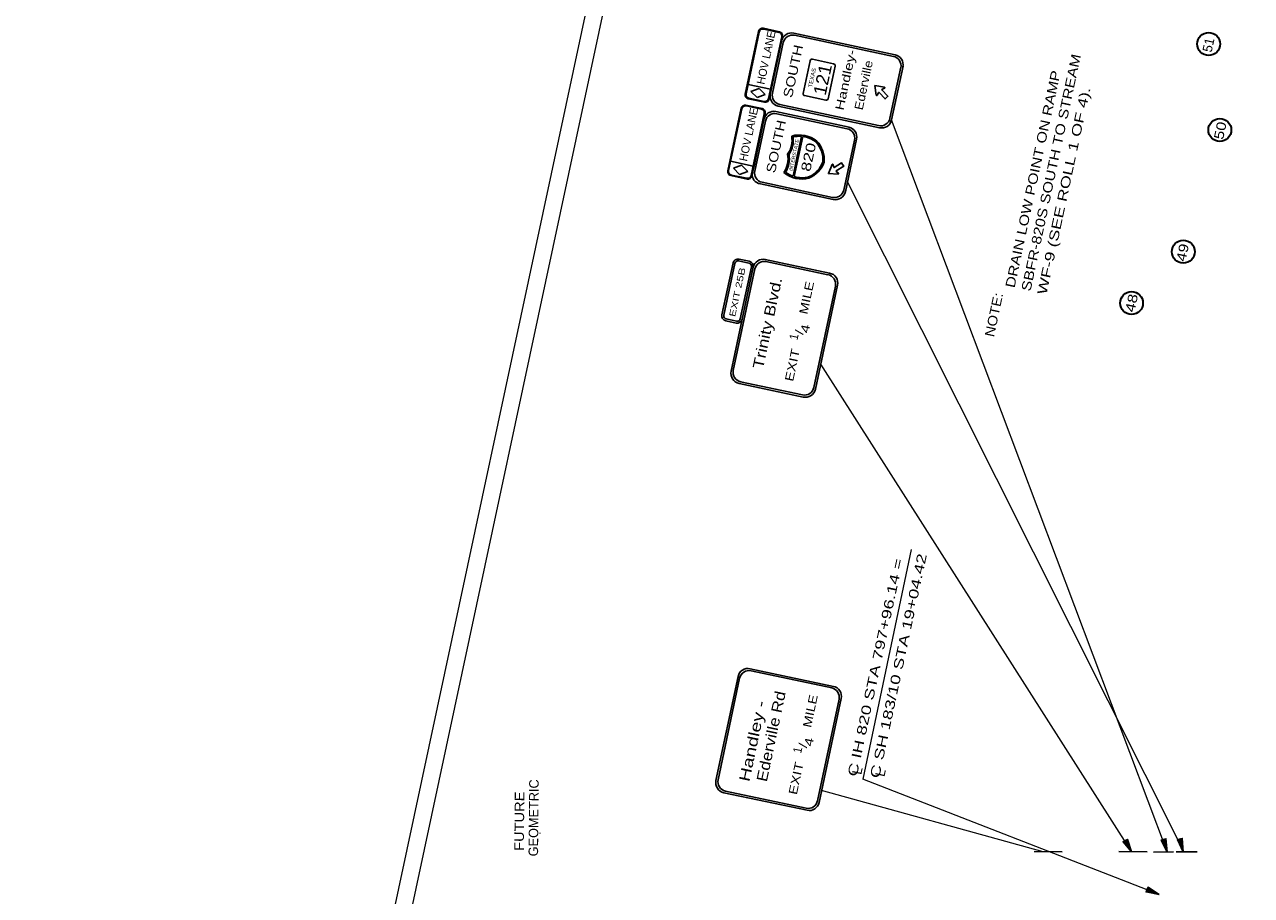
# Model space of a CAD drawing. Extents: x 2363411 to 2369702, y 6977197 to 6988655.
# Drawn here: x 2363411 to 2365218, y 6980518 to 6981800 of the extents above; entities that cross this region are included whole.
import ezdxf
from ezdxf.enums import TextEntityAlignment as Align

# ---------------------------------------------------------------- set-up
doc = ezdxf.new("R2010")
doc.units = 0
doc.header["$LTSCALE"] = 5.6
for name, color, linetype, lineweight in [('1', 7, 'Continuous', 25), ('10', 7, 'Continuous', 13), ('17', 7, 'Continuous', 35), ('25', 7, 'Continuous', 25), ('3', 7, 'Continuous', 13), ('48', 7, 'Continuous', 25), ('63', 7, 'Continuous', 13)]:
    doc.layers.add(name, color=color, linetype=linetype, lineweight=lineweight)

msp = doc.modelspace()

# ---------------------------------------------------------------- hatches: boundary and pattern name
at = {"layer": '1'}
for points in [[(2365041.105, 6980581.652), (2365034.805, 6980600.142), (2365028.531, 6980596.602)], [(2365093.482, 6980581.643), (2365091.506, 6980601.077), (2365084.596, 6980599.04)], [(2365116.849, 6980582.029), (2365115.724, 6980601.531), (2365108.732, 6980599.799)]]:
    msp.add_hatch(color=256, dxfattribs=at).paths.add_polyline_path(points)
at = {"layer": '48'}
msp.add_hatch(color=256, dxfattribs=at).paths.add_polyline_path([(2365081.609, 6980519.005), (2365065.21, 6980529.633), (2365062.48, 6980522.971)])

# ---------------------------------------------------------------- linework, layer by layer
at = {"layer": '1'}
for p, q in [((2364510.557, 6981704.003), (2364527.278, 6981782.177)), ((2364543.681, 6981787.196), (2364692.927, 6981755.318)), ((2364544.934, 6981784.062), (2364690.505, 6981752.959)), ((2364512.307, 6981698.738), (2364528.246, 6981773.246)), ((2364567.849, 6981746.577), (2364557.555, 6981698.419)), ((2364602.418, 6981742.056), (2364571.184, 6981748.736)), ((2364594.288, 6981690.57), (2364604.584, 6981738.72)), ((2364701.432, 6981736.854), (2364685.386, 6981661.758)), ((2364704.6, 6981738.247), (2364687.74, 6981659.336)), ((2364663.102, 6981710.136), (2364677.204, 6981707.364)), ((2364665.246, 6981695.932), (2364663.102, 6981710.136)), ((2364559.721, 6981695.083), (2364590.953, 6981688.404)), ((2364668.504, 6981699.384), (2364666.672, 6981695.673)), ((2364677.394, 6981705.923), (2364673.59, 6981704.237)), ((2364517.537, 6981671.682), (2364625.116, 6981648.692)), ((2364520.713, 6981679.695), (2364669.939, 6981647.803)), ((2364668.693, 6981650.945), (2364523.12, 6981682.047)), ((2364485, 6981589.302), (2364501.644, 6981669.029)), ((2364486.315, 6981583.843), (2364502.107, 6981657.73)), ((2364518.791, 6981668.549), (2364622.321, 6981646.423)), ((2364555.219, 6981635.153), (2364548.954, 6981605.815)), ((2364557.111, 6981634.943), (2364550.803, 6981605.422)), ((2364633.139, 6981629.739), (2364617.42, 6981556.186)), ((2364636.274, 6981630.985), (2364619.711, 6981553.461)), ((2364542.687, 6981576.479), (2364548.954, 6981605.815)), ((2364544.496, 6981575.879), (2364550.803, 6981605.422)), ((2364601.686, 6981593.602), (2364602.575, 6981589.537)), ((2364603.32, 6981589.213), (2364603.332, 6981589.221)), ((2364606.305, 6981583.579), (2364609.573, 6981581.04)), ((2364494.786, 6981565.14), (2364601.985, 6981542.224)), ((2364600.739, 6981545.366), (2364497.193, 6981567.492)), ((2364478.348, 6981451.323), (2364463.233, 6981454.551)), ((2364438.039, 6981372.497), (2364454.334, 6981448.786)), ((2364440.786, 6981371.909), (2364457.081, 6981448.196)), ((2364484.115, 6981442.419), (2364451.622, 6981289.319)), ((2364486.473, 6981439.977), (2364454.754, 6981290.576)), ((2364477.759, 6981448.568), (2364462.646, 6981451.797)), ((2364481.367, 6981443.005), (2364465.062, 6981366.724)), ((2364501.574, 6981454.088), (2364596.575, 6981433.924)), ((2364594.15, 6981431.537), (2364502.561, 6981450.984)), ((2364573.329, 6981265.404), (2364605.04, 6981414.811)), ((2364575.685, 6981262.985), (2364608.18, 6981416.062)), ((2364459.498, 6981363.118), (2364444.392, 6981366.347)), ((2364458.91, 6981360.363), (2364443.804, 6981363.598)), ((2364465.216, 6981273.941), (2364556.579, 6981254.543)), ((2364463.199, 6981271.47), (2364557.829, 6981251.38)), ((2364479.58, 6980851.486), (2364602.009, 6980825.5)), ((2364599.584, 6980823.113), (2364480.846, 6980848.324)), ((2364461.746, 6980839.898), (2364429.253, 6980686.798)), ((2364464.104, 6980837.456), (2364432.385, 6980688.055)), ((2364578.763, 6980656.98), (2364610.474, 6980806.387)), ((2364581.119, 6980654.561), (2364613.614, 6980807.638)), ((2364440.827, 6980668.949), (2364563.263, 6980642.956)), ((2364443.275, 6980671.329), (2364562.013, 6980646.119)), ((2364897.562, 6980582.331), (2364938.878, 6980581.843)), ((2365022.463, 6980582.571), (2365063.779, 6980582.083)), ((2365073.225, 6980581.554), (2365102.551, 6980581.713)), ((2365106.745, 6980581.736), (2365137.772, 6980581.904))]:
    msp.add_line(p, q, dxfattribs=at)
at = {"layer": '1', "lineweight": 13}
for p, q in [((2365092.359, 6980584.889), (2364687.743, 6981659.338)), ((2365116.035, 6980586.052), (2364622.844, 6981568.126)), ((2365041.084, 6980582.351), (2364583.493, 6981299.766)), ((2364910.747, 6980581.94), (2364584.814, 6980671.968))]:
    msp.add_line(p, q, dxfattribs=at)
at = {"layer": '1'}
for points in [[(2364673.432, 6981703.432), (2364682.339, 6981694.13), (2364680.291, 6981692.175), (2364678.234, 6981690.223), (2364669.33, 6981699.511)], [(2364609.032, 6981579.693), (2364594.688, 6981580.448), (2364600.237, 6981593.708)], [(2364603.332, 6981589.221), (2364614.233, 6981596.077), (2364615.735, 6981593.676), (2364617.238, 6981591.27), (2364606.346, 6981584.414)]]:
    msp.add_lwpolyline(points, dxfattribs=at)
for points in [[(2365041.105, 6980581.652), (2365034.805, 6980600.142), (2365028.531, 6980596.602)], [(2365093.482, 6980581.643), (2365091.506, 6980601.077), (2365084.596, 6980599.04)], [(2365116.849, 6980582.029), (2365115.724, 6980601.531), (2365108.732, 6980599.799)]]:
    msp.add_lwpolyline(points, close=True, dxfattribs=at)
for centre, radius, start, end in [((2364540.556, 6981772.532), 15.001, 77.94013, 167.94013), ((2364541.998, 6981770.307), 14.063, 77.94013, 167.94013), ((2364570.599, 6981745.983), 2.813, 77.93906, 167.93906), ((2364687.567, 6981739.206), 14.063, 347.94013, 77.94013), ((2364689.792, 6981740.648), 15.001, 347.94013, 77.94013), ((2364601.827, 6981739.31), 2.813, 347.93906, 77.93906), ((2364677.076, 6981706.614), 0.759, 293.5894, 78.97054), ((2364523.837, 6981694.356), 15.001, 167.94013, 257.94013), ((2364526.063, 6981695.798), 14.063, 167.94013, 257.94013), ((2364560.311, 6981697.83), 2.813, 167.93906, 257.93906), ((2364591.538, 6981691.158), 2.813, 257.93906, 347.93906), ((2364665.99, 6981696.016), 0.759, 188.44753, 333.82867), ((2364668.958, 6981699.174), 0.506, 43.70904, 153.69214), ((2364673.788, 6981703.791), 0.506, 113.72593, 223.70904), ((2364514.413, 6981657.019), 15.001, 77.94013, 167.94013), ((2364515.855, 6981654.793), 14.063, 77.94013, 167.94013), ((2364671.632, 6981664.698), 14.063, 257.94013, 347.94013), ((2364673.074, 6981662.472), 15.001, 257.94013, 347.94013), ((2364505.249, 6981629.415), 35.984, 325.11963, 9.96995), ((2364551.904, 6981595.218), 41.954, 51.80243, 105.50481), ((2364551.904, 6981595.218), 40.064, 85.24888, 103.11363), ((2364619.386, 6981632.675), 14.063, 347.94013, 77.94013), ((2364621.611, 6981634.117), 15.001, 347.94013, 77.94013), ((2364505.249, 6981629.415), 37.874, 326.31755, 7.31439), ((2364551.904, 6981595.218), 40.064, 52.01897, 82.53095), ((2364547.913, 6981600.617), 38.808, 355.77729, 42.42367), ((2364547.913, 6981600.617), 40.698, 355.41114, 42.64704), ((2364499.417, 6981602.12), 35.984, 325.90855, 10.75886), ((2364499.417, 6981602.12), 37.874, 328.56411, 9.56095), ((2364500.136, 6981581.243), 14.063, 167.94013, 257.94013), ((2364555.974, 6981614.264), 41.954, 230.37369, 284.07606), ((2364555.974, 6981614.264), 40.064, 232.76486, 250.62962), ((2364550.124, 6981610.968), 38.808, 293.45483, 340.10121), ((2364550.124, 6981610.968), 40.698, 293.23145, 340.46735), ((2364600.947, 6981593.43), 0.759, 11.99531, 157.37645), ((2364603.05, 6981589.642), 0.506, 192.13184, 302.11494), ((2364606.603, 6981583.981), 0.506, 122.11494, 232.09805), ((2364609.1, 6981580.44), 0.759, 266.85344, 52.23458), ((2364555.974, 6981614.264), 40.064, 253.34754, 283.85953), ((2364603.667, 6981559.124), 14.063, 257.94013, 347.94013), ((2364605.109, 6981556.899), 15.001, 257.94013, 347.94013), ((2364461.67, 6981447.215), 7.501, 77.93922, 167.93922), ((2364461.67, 6981447.215), 4.688, 77.93922, 167.93922), ((2364476.78, 6981443.986), 4.688, 347.93922, 77.93922), ((2364476.78, 6981443.986), 7.501, 347.93922, 77.93922), ((2364498.831, 6981439.292), 15.049, 78.01448, 168.01448), ((2364500.281, 6981437.061), 14.108, 78.01448, 168.01447), ((2364591.237, 6981417.752), 14.108, 348.01448, 78.01448), ((2364593.467, 6981419.202), 15.049, 348.01447, 78.01447), ((2364445.37, 6981370.93), 7.501, 167.93922, 257.93922), ((2364445.37, 6981370.93), 4.688, 167.93922, 257.93922), ((2364460.48, 6981367.701), 7.501, 257.93922, 347.93922), ((2364460.48, 6981367.701), 4.688, 257.93922, 347.93922), ((2364466.33, 6981286.197), 15.049, 168.01448, 258.01448), ((2364468.561, 6981287.647), 14.108, 168.01447, 258.01447), ((2364559.517, 6981268.338), 14.108, 258.01447, 348.01447), ((2364560.966, 6981266.107), 15.049, 258.01447, 348.01447), ((2364476.462, 6980836.77), 15.049, 78.01448, 168.01448), ((2364477.912, 6980834.54), 14.108, 78.01448, 168.01447), ((2364596.67, 6980809.328), 14.108, 348.01448, 78.01448), ((2364598.901, 6980810.777), 15.049, 348.01447, 78.01447), ((2364443.961, 6980683.676), 15.049, 168.01448, 258.01448), ((2364446.192, 6980685.125), 14.108, 168.01447, 258.01447), ((2364564.951, 6980659.914), 14.108, 258.01447, 348.01447), ((2364566.4, 6980657.683), 15.049, 258.01447, 348.01447)]:
    msp.add_arc(centre, radius, start, end, dxfattribs=at)
msp.add_ellipse((2364497.948, 6981577.732), major_axis=(-15.18, 0), ratio=0.848877, start_param=6.07270093, end_param=7.64349725, dxfattribs=at)
at = {"layer": '10'}
for p, q in [((2363411.416, 6977949.748), (2365605.51, 6988218.434)), ((2363435.864, 6977944.524), (2365629.958, 6988213.21))]:
    msp.add_line(p, q, dxfattribs=at)
at = {"layer": '17'}
for centre in [(2365154.488, 6981771.164), (2365170.93, 6981644.587), (2365117.144, 6981465.378), (2365041.015, 6981389.712)]:
    msp.add_circle(centre, 16.828, dxfattribs=at)
at = {"layer": '3'}
msp.add_line((2364170.317, 6980609.105), (2364169.356, 6980609.076), dxfattribs=at)
at = {"layer": '48'}
for p, q in [((2364472.286, 6981697.473), (2364491.999, 6981789.716)), ((2364473.518, 6981697.965), (2364492.916, 6981788.762)), ((2364499.009, 6981794.257), (2364522.735, 6981789.187)), ((2364521.781, 6981788.261), (2364499.498, 6981793.022)), ((2364526.038, 6981781.683), (2364506.641, 6981690.886)), ((2364527.277, 6981782.177), (2364507.572, 6981689.932)), ((2364476.443, 6981711.654), (2364509.566, 6981704.576)), ((2364476.83, 6981690.459), (2364500.687, 6981685.361)), ((2364477.785, 6981691.388), (2364500.069, 6981686.625)), ((2364480.665, 6981701.255), (2364492.593, 6981705.755)), ((2364489.712, 6981692.272), (2364480.665, 6981701.255)), ((2364489.712, 6981692.272), (2364501.64, 6981696.773)), ((2364501.64, 6981696.773), (2364492.593, 6981705.755)), ((2364446.649, 6981584.326), (2364466.362, 6981676.569)), ((2364447.881, 6981584.818), (2364467.279, 6981675.615)), ((2364473.371, 6981681.11), (2364497.097, 6981676.041)), ((2364496.144, 6981675.115), (2364473.86, 6981679.876)), ((2364500.401, 6981668.536), (2364481.004, 6981577.739)), ((2364501.64, 6981669.03), (2364481.935, 6981576.785)), ((2364450.806, 6981598.507), (2364483.929, 6981591.429)), ((2364455.028, 6981588.108), (2364466.956, 6981592.608)), ((2364464.075, 6981579.125), (2364455.028, 6981588.108)), ((2364464.075, 6981579.125), (2364476.003, 6981583.626)), ((2364476.003, 6981583.626), (2364466.956, 6981592.608)), ((2364451.193, 6981577.313), (2364475.049, 6981572.215)), ((2364452.148, 6981578.242), (2364474.431, 6981573.479))]:
    msp.add_line(p, q, dxfattribs=at)
at = {"layer": '48', "lineweight": 13}
for p in [(2364716.596, 6981026.866), (2365081.609, 6980519.005)]:
    msp.add_line(p, (2364645.554, 6980688.928), dxfattribs=at)
at = {"layer": '48'}
msp.add_lwpolyline([(2365081.609, 6980519.005), (2365065.21, 6980529.633), (2365062.48, 6980522.971)], close=True, dxfattribs=at)
for centre, radius, start, end in [((2364497.777, 6981788.48), 5.909, 77.93633, 167.93633), ((2364498.345, 6981787.603), 5.54, 77.93633, 167.93633), ((2364520.623, 6981782.839), 5.54, 347.93633, 77.93633), ((2364521.5, 6981783.407), 5.909, 347.93633, 77.93633), ((2364478.065, 6981696.237), 5.909, 167.93575, 257.93575), ((2364478.942, 6981696.805), 5.54, 167.93575, 257.93575), ((2364501.227, 6981692.042), 5.54, 257.93575, 347.93575), ((2364501.795, 6981691.166), 5.909, 257.93575, 347.93575), ((2364472.139, 6981675.333), 5.909, 77.93633, 167.93633), ((2364472.707, 6981674.456), 5.54, 77.93633, 167.93633), ((2364494.985, 6981669.693), 5.54, 347.93633, 77.93633), ((2364495.862, 6981670.261), 5.909, 347.93633, 77.93633), ((2364452.428, 6981583.091), 5.909, 167.93575, 257.93575), ((2364453.304, 6981583.658), 5.54, 167.93575, 257.93575), ((2364475.589, 6981578.896), 5.54, 257.93575, 347.93575), ((2364476.157, 6981578.019), 5.909, 257.93575, 347.93575)]:
    msp.add_arc(centre, radius, start, end, dxfattribs=at)

# ---------------------------------------------------------------- texts
at = {"layer": '1'}
for s, height, rotation, width, p in [('SOUTH', 13.5, 77.94, 1.25, (2364549.388, 6981729.703)), ('Handley-', 12.54, 78.014, 1.35, (2364626.206, 6981716.981)), ('Ederville', 12.54, 78.014, 1.15, (2364652.75, 6981709.211)), ('SOUTH', 13.5, 77.94, 1.25, (2364524.305, 6981618.872)), ('EXIT 25B', 9.188, 77.939, 1.4, (2364465.091, 6981404.909)), ('Trinity Blvd.', 15.68, 78.014, 1.25, (2364512.636, 6981358.757)), ('MILE', 12.54, 78.014, 1.25, (2364568.768, 6981396.263)), ('/', 12.54, 78.014, 1.3, (2364558.016, 6981345.592)), ('4', 12.54, 78.014, 1.35, (2364566.822, 6981350.722)), ('1', 12.54, 78.014, 0.95, (2364550.061, 6981338.85)), ('EXIT', 12.54, 78.014, 1.3, (2364547.737, 6981297.173)), ('Ederville Rd', 15.68, 78.014, 1.2, (2364518.069, 6980750.332)), ('MILE', 12.54, 78.014, 1.25, (2364574.202, 6980787.839)), ('Handley -', 15.68, 78.014, 1.35, (2364490.859, 6980743.392)), ('1', 12.54, 78.014, 0.95, (2364555.495, 6980730.426)), ('/', 12.54, 78.014, 1.3, (2364563.45, 6980737.168)), ('4', 12.54, 78.014, 1.35, (2364572.256, 6980742.298)), ('EXIT', 12.54, 78.014, 1.3, (2364553.171, 6980688.749)), ('FUTURE ', 14, 89.491, 1.15, (2364146.801, 6980629.817))]:
    msp.add_text(s, height=height, rotation=rotation, dxfattribs=dict(at, width=width)).set_placement(p, align=Align.CENTER)
for s, height, width, p in [('TEXAS', 6, 1.1, (2364570.682, 6981706.698)), ('121', 18.75, 1.1, (2364590.578, 6981694.296)), ('INTERSTATE', 5.198, 1.1, (2364541.806, 6981583.948)), ('820', 14.18, 1.35, (2364567.874, 6981582.199))]:
    msp.add_text(s, height=height, rotation=77.939, dxfattribs=dict(at, width=width)).set_placement(p)
msp.add_text('GEOMETRIC', height=14, rotation=89.491, dxfattribs=at).set_placement((2364167.82, 6980631.853), align=Align.CENTER)
at = {"layer": '17'}
msp.add_text('51', height=14, rotation=77.939, dxfattribs=at).set_placement((2365161.023, 6981768.248), align=Align.CENTER)
for s, width, p in [('50', 1.25, (2365178.367, 6981642.253)), ('49', 1.25, (2365122.945, 6981462.674)), ('48', 1.3, (2365047.879, 6981388.335))]:
    msp.add_text(s, height=14, rotation=77.939, dxfattribs=dict(at, width=width)).set_placement(p, align=Align.CENTER)
at = {"layer": '25'}
for s, width, p in [('C IH 820 STA 797+96.14 =', 1.45, (2364636.486, 6980691.807)), ('C SH 183/10 STA 19+04.42', 1.45, (2364669.39, 6980689.358)), ('L', 1.05, (2364643.048, 6980694.638)), ('L', 1.05, (2364677.146, 6980691.588))]:
    msp.add_text(s, height=14, rotation=77.939, dxfattribs=dict(at, width=width)).set_placement(p)
at = {"layer": '48'}
for p in [(2364508.74, 6981749.876), (2364483.102, 6981636.73)]:
    msp.add_text('HOV LANE', height=11.82, rotation=77.935, dxfattribs=at).set_placement(p, align=Align.CENTER)
at = {"layer": '63'}
for s, width, p in [('SBFR-820S SOUTH TO STREAM', 1.25, (2364892.154, 6981406.197)), ('DRAIN LOW POINT ON RAMP', 1.25, (2364868.682, 6981411.212)), ('WF-9 (SEE ROLL 1 OF 4).', 1.4, (2364915.625, 6981401.182))]:
    msp.add_text(s, height=14, rotation=77.939, dxfattribs=dict(at, width=width)).set_placement(p)
at = {"layer": '63', "width": 1.15}
msp.add_text('NOTE:', height=14, rotation=77.939, dxfattribs=at).set_placement((2364845.243, 6981371.118), align=Align.CENTER)

doc.saveas('drawing.dxf')
